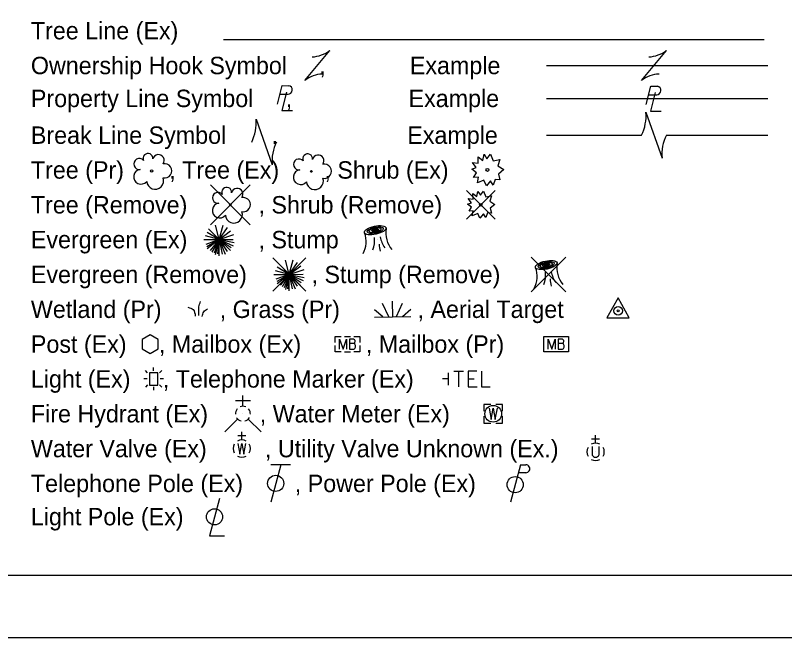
# Model space of a CAD drawing. Extents: x 0 to 34.3, y -4.1 to 22.
# Drawn here: x 8.07 to 14.26, y 0 to 5 of the extents above; entities that cross this region are included whole.
import ezdxf

# ---------------------------------------------------------------- set-up
doc = ezdxf.new("R2010")
doc.units = 0
for name, color, linetype in [('GM_X_Adjacent_County', 7, 'Continuous'), ('GM_X_County', 7, 'Continuous'), ('GM_X_Section', 7, 'Continuous')]:
    doc.layers.add(name, color=color, linetype=linetype)

msp = doc.modelspace()

# ---------------------------------------------------------------- linework, layer by layer
at = {"layer": 'GM_X_Adjacent_County'}
for p, q in [((9.7458, 4.8098), (14.0958, 4.8098)), ((10.4008, 4.4798), (10.6008, 4.7198)), ((13.109, 4.4798), (13.309, 4.7198)), ((10.5008, 4.5998), (10.5008, 4.5998)), ((12.3436, 4.5998), (14.1259, 4.5998)), ((13.209, 4.5998), (13.209, 4.5998)), ((10.2011, 4.3688), (10.2659, 4.3688)), ((10.2412, 4.3376), (10.2412, 4.3376)), ((12.3436, 4.3352), (14.1259, 4.3352)), ((13.1667, 4.3647), (13.2316, 4.3647)), ((13.2068, 4.3336), (13.2068, 4.3336)), ((13.144, 4.224), (13.274, 3.8558)), ((10.0084, 4.1684), (10.1384, 3.8001)), ((12.3436, 4.0398), (13.1091, 4.0398)), ((13.209, 4.0399), (13.209, 4.0399)), ((13.3089, 4.0398), (14.1259, 4.0398)), ((10.0734, 3.9842), (10.0734, 3.9842)), ((9.6412, 3.6401), (9.962, 3.3194)), ((9.962, 3.6401), (9.6412, 3.3194)), ((11.7003, 3.5957), (11.9321, 3.3639)), ((11.9321, 3.5957), (11.7003, 3.3639)), ((9.8016, 3.4798), (9.8016, 3.4798)), ((11.8162, 3.4798), (11.8162, 3.4798)), ((9.7121, 3.1996), (9.6248, 3.2868)), ((9.7121, 3.1996), (9.6812, 3.3149)), ((9.7121, 3.1996), (9.7435, 3.317)), ((9.7121, 3.1996), (9.7785, 3.2967)), ((9.7121, 3.1996), (9.6017, 3.2292)), ((9.7121, 3.1996), (9.6144, 3.257)), ((9.7121, 3.1996), (9.8035, 3.2697)), ((9.7121, 3.1996), (9.8305, 3.2398)), ((9.5887, 3.1996), (9.7121, 3.1996)), ((9.7121, 3.1996), (9.6048, 3.1605)), ((9.7121, 3.1996), (9.6125, 3.1425)), ((9.7121, 3.1996), (9.6144, 3.1247)), ((9.7121, 3.1996), (9.6385, 3.1129)), ((9.7121, 3.1996), (9.6541, 3.0992)), ((9.7121, 3.1996), (9.6705, 3.0911)), ((9.7121, 3.1996), (9.6805, 3.0782)), ((9.7121, 3.1996), (9.6985, 3.0848)), ((9.7121, 3.1996), (9.8248, 3.2019)), ((9.7121, 3.0686), (9.7121, 3.1996)), ((9.7121, 3.1996), (9.7351, 3.0837)), ((9.7121, 3.1996), (9.7604, 3.0829)), ((9.7121, 3.1996), (9.7755, 3.1048)), ((9.7121, 3.1996), (9.8018, 3.1115)), ((9.7121, 3.1996), (9.8076, 3.1357)), ((9.7121, 3.1996), (9.8237, 3.151)), ((9.7121, 3.1996), (9.8328, 3.1756)), ((10.9857, 3.1998), (10.9857, 3.1998)), ((10.1425, 3.0534), (10.4098, 2.7861)), ((10.4098, 3.0534), (10.1425, 2.7861)), ((10.2761, 2.9198), (10.2452, 3.0351)), ((10.2761, 2.9198), (10.3075, 3.0373)), ((12.2223, 3.0589), (12.5004, 2.7808)), ((12.5004, 3.0589), (12.2223, 2.7808)), ((10.2761, 2.9198), (10.1784, 2.9772)), ((10.2761, 2.9198), (10.1888, 3.007)), ((10.2761, 2.9198), (10.3425, 3.0169)), ((10.2761, 2.9198), (10.3675, 2.9899)), ((10.1527, 2.9198), (10.2761, 2.9198)), ((10.2761, 2.9198), (10.1658, 2.9494)), ((10.2761, 2.9198), (10.1688, 2.8808)), ((10.2761, 2.9198), (10.1765, 2.8628)), ((10.2761, 2.9198), (10.1784, 2.8449)), ((10.2761, 2.9198), (10.2025, 2.8331)), ((10.2761, 2.9198), (10.2181, 2.8194)), ((10.2761, 2.9198), (10.2345, 2.8113)), ((10.2761, 2.9198), (10.2445, 2.7984)), ((10.2761, 2.9198), (10.2626, 2.805)), ((10.2761, 2.9198), (10.3945, 2.96)), ((10.2761, 2.9198), (10.3888, 2.9221)), ((10.2761, 2.7888), (10.2761, 2.9198)), ((10.2761, 2.9198), (10.2991, 2.8039)), ((10.2761, 2.9198), (10.3244, 2.8031)), ((10.2761, 2.9198), (10.3395, 2.825)), ((10.2761, 2.9198), (10.3658, 2.8318)), ((10.2761, 2.9198), (10.3716, 2.8559)), ((10.2761, 2.9198), (10.3877, 2.8713)), ((10.2761, 2.9198), (10.3968, 2.8959)), ((10.2761, 2.9198), (10.2761, 2.9198)), ((12.3613, 2.9198), (12.3613, 2.9198)), ((12.3613, 2.9198), (12.3613, 2.9198)), ((11.0777, 2.5794), (11.0256, 2.6855)), ((11.1077, 2.5798), (11.1058, 2.7053)), ((11.1377, 2.5803), (11.1866, 2.6878)), ((11.029, 2.5787), (10.9607, 2.6358)), ((11.1864, 2.581), (11.253, 2.6401)), ((10.9616, 2.5776), (11.2538, 2.582)), ((10.7189, 2.4209), (10.7689, 2.4209)), ((10.7444, 2.3598), (10.7444, 2.3598)), ((12.4226, 2.3598), (12.4226, 2.3598)), ((10.7189, 2.2987), (10.7689, 2.2987)), ((9.1848, 2.1438), (9.1848, 2.1704)), ((9.1365, 2.1282), (9.118, 2.147)), ((9.2515, 2.147), (9.2329, 2.1282)), ((11.5574, 2.0298), (11.5574, 2.1298)), ((9.1326, 2.0801), (9.106, 2.0801)), ((9.1848, 2.0798), (9.1848, 2.0798)), ((9.2635, 2.0801), (9.2369, 2.0801)), ((11.5574, 2.0798), (11.5077, 2.0798)), ((9.1365, 2.0314), (9.118, 2.0126)), ((9.1848, 2.0158), (9.1848, 1.9892)), ((9.2515, 2.0126), (9.2329, 2.0314)), ((9.9028, 1.86), (9.9028, 1.946)), ((9.9628, 1.903), (9.8428, 1.903)), ((9.9029, 1.7998), (9.9029, 1.7998)), ((9.9029, 1.7998), (9.9029, 1.7998)), ((11.9165, 1.7998), (11.9165, 1.7998)), ((9.8606, 1.7574), (9.7566, 1.6535)), ((9.9452, 1.7574), (10.0492, 1.6535)), ((9.9255, 1.6216), (9.8619, 1.6216)), ((9.8938, 1.5898), (9.8938, 1.6534)), ((12.7399, 1.5634), (12.7399, 1.6269)), ((12.7717, 1.5952), (12.7081, 1.5952)), ((9.8938, 1.5198), (9.8938, 1.5198)), ((12.7127, 1.5365), (12.7127, 1.4676)), ((12.7399, 1.4934), (12.7399, 1.4934)), ((12.767, 1.5365), (12.767, 1.4676)), ((10.2068, 1.3898), (10.1265, 1.0898)), ((10.2868, 1.3898), (10.1268, 1.3898)), ((12.1358, 1.3898), (12.0554, 1.0898)), ((12.1358, 1.3898), (12.1783, 1.3898)), ((12.1187, 1.3261), (12.1783, 1.3261))]:
    msp.add_line(p, q, dxfattribs=at)
for points in [[(10.1801, 4.2892), (10.2192, 4.4375), (10.2708, 4.4374)], [(13.1457, 4.2851), (13.1848, 4.4334), (13.2365, 4.4333)], [(10.2545, 4.3856), (10.2149, 4.2378), (10.3023, 4.2378)], [(13.2201, 4.3816), (13.1806, 4.2337), (13.2679, 4.2337)], [(11.8649, 3.8503), (11.8952, 3.8871), (11.9159, 3.8344), (11.9705, 3.8434), (11.9536, 3.7928), (12.0009, 3.7631), (11.958, 3.7263), (11.9705, 3.6806), (11.9329, 3.6841), (11.9166, 3.6384), (11.8952, 3.673), (11.8613, 3.6321), (11.8399, 3.6765), (11.7889, 3.655), (11.7984, 3.7021), (11.7579, 3.6979), (11.7815, 3.7374), (11.7431, 3.7658), (11.78, 3.779), (11.7497, 3.8191), (11.7963, 3.8136), (11.7948, 3.8656), (11.8324, 3.8371), (11.8428, 3.8864), (11.8649, 3.8503)], [(11.8126, 3.5567), (11.8383, 3.588), (11.8559, 3.5432), (11.9023, 3.5509), (11.888, 3.5079), (11.9281, 3.4826), (11.8917, 3.4513), (11.9023, 3.4125), (11.8703, 3.4154), (11.8565, 3.3766), (11.8383, 3.406), (11.8095, 3.3713), (11.7913, 3.409), (11.7479, 3.3907), (11.7561, 3.4307), (11.7216, 3.4272), (11.7417, 3.4608), (11.709, 3.4849), (11.7404, 3.4961), (11.7146, 3.5302), (11.7542, 3.5256), (11.753, 3.5697), (11.785, 3.5455), (11.7938, 3.5874), (11.8126, 3.5567)], [(9.0916, 2.3223), (9.1565, 2.2848), (9.2214, 2.3223), (9.2214, 2.3973), (9.1565, 2.4348), (9.0916, 2.3973), (9.0916, 2.3223)], [(10.6444, 2.3724), (10.6444, 2.4209), (10.6929, 2.4209)], [(10.7948, 2.4209), (10.8444, 2.4209), (10.8444, 2.3724)], [(10.6796, 2.3198), (10.6796, 2.3998), (10.7086, 2.3198), (10.7363, 2.3998), (10.7363, 2.3198)], [(10.7955, 2.3633), (10.7987, 2.3664), (10.8006, 2.3683), (10.8018, 2.3702), (10.8025, 2.3715), (10.8037, 2.374), (10.8044, 2.3759), (10.8056, 2.3803), (10.8056, 2.3822), (10.8056, 2.3847), (10.805, 2.3885), (10.8037, 2.3916), (10.8018, 2.3941), (10.7987, 2.3967), (10.7962, 2.3979), (10.7949, 2.3986), (10.7918, 2.3998), (10.7609, 2.3998), (10.7609, 2.3198), (10.7955, 2.3198), (10.7999, 2.3223), (10.8037, 2.3255), (10.8069, 2.3305), (10.8088, 2.3362), (10.8094, 2.3419), (10.8094, 2.3456), (10.8081, 2.3494), (10.8056, 2.3551), (10.8025, 2.3589), (10.7955, 2.3633), (10.7609, 2.3633)], [(12.3578, 2.3198), (12.3578, 2.3998), (12.3867, 2.3198), (12.4144, 2.3998), (12.4144, 2.3198)], [(12.4737, 2.3633), (12.4768, 2.3664), (12.4787, 2.3683), (12.48, 2.3702), (12.4806, 2.3715), (12.4818, 2.374), (12.4825, 2.3759), (12.4837, 2.3803), (12.4837, 2.3822), (12.4837, 2.3847), (12.4831, 2.3885), (12.4818, 2.3916), (12.48, 2.3941), (12.4768, 2.3967), (12.4743, 2.3979), (12.473, 2.3986), (12.4699, 2.3998), (12.439, 2.3998), (12.439, 2.3198), (12.4737, 2.3198), (12.4781, 2.3223), (12.4818, 2.3255), (12.485, 2.3305), (12.4869, 2.3362), (12.4875, 2.3419), (12.4875, 2.3456), (12.4863, 2.3494), (12.4837, 2.3551), (12.4806, 2.3589), (12.4737, 2.3633), (12.439, 2.3633)], [(10.6929, 2.2987), (10.6444, 2.2987), (10.6444, 2.3472)], [(10.8444, 2.3472), (10.8444, 2.2987), (10.7948, 2.2987)], [(11.5983, 2.1419), (11.676, 2.1419)], [(11.6376, 2.1419), (11.6376, 2.0169)], [(11.7833, 2.1419), (11.7154, 2.1419), (11.7154, 2.0169), (11.7882, 2.0169)], [(11.8226, 2.1419), (11.8226, 2.0169), (11.8906, 2.0169)], [(11.7154, 2.0799), (11.7636, 2.0799)], [(11.8965, 1.8748), (11.8415, 1.8748), (11.8415, 1.8198)], [(11.9915, 1.8198), (11.9915, 1.8748), (11.9365, 1.8748)], [(11.8831, 1.8448), (11.8998, 1.7548), (11.9165, 1.8448), (11.9331, 1.7548), (11.9498, 1.8448)], [(11.8415, 1.7798), (11.8415, 1.7248), (11.8965, 1.7248)], [(11.9365, 1.7248), (11.9915, 1.7248), (11.9915, 1.7798)], [(9.8619, 1.5608), (9.8778, 1.4746), (9.8938, 1.5608), (9.9098, 1.4746), (9.9256, 1.5608)], [(9.714, 1.1186), (9.6353, 0.8193), (9.7535, 0.8193)]]:
    msp.add_lwpolyline(points, dxfattribs=at)
for points in [[(12.8307, 2.5698), (13.0107, 2.5698), (12.9207, 2.7308)], [(12.3226, 2.4209), (12.5226, 2.4209), (12.5226, 2.2987), (12.3226, 2.2987)], [(9.1515, 2.0298), (9.218, 2.0298), (9.218, 2.1298), (9.1515, 2.1298)]]:
    msp.add_lwpolyline(points, close=True, dxfattribs=at)
for centre, radius in [((9.1686, 3.7517), 0.0084), ((10.4532, 3.7483), 0.0072), ((11.8692, 3.7598), 0.0115), ((9.8016, 3.4798), 0.0072), ((11.8162, 3.4798), 0.00979), ((12.9207, 2.6276), 0.035), ((12.9207, 2.6276), 0.008), ((11.9165, 1.7998), 0.0675), ((10.1666, 1.2398), 0.065), ((12.0929, 1.2298), 0.065), ((9.6747, 0.9709), 0.065)]:
    msp.add_circle(centre, radius, dxfattribs=at)
for centre, radius, start, end in [((10.4427, 4.9348), 0.2668, 273.69448, 306.33701), ((13.1509, 4.9348), 0.2668, 273.69448, 306.33701), ((10.5589, 4.2649), 0.2668, 93.69448, 126.33701), ((13.2671, 4.2649), 0.2668, 93.69448, 126.33701), ((10.2656, 4.4033), 0.0345, 270.47098, 81.3281), ((13.2313, 4.3992), 0.0345, 270.47098, 81.3281), ((12.8121, 4.1915), 0.3335, 332.94224, 5.58476), ((9.6764, 4.1359), 0.3335, 332.94224, 5.58476), ((13.606, 3.8882), 0.3335, 152.94224, 185.58476), ((10.4703, 3.8326), 0.3335, 152.94224, 185.58476), ((9.0693, 3.8076), 0.0441, 39.06254, 279.54124), ((9.1391, 3.8527), 0.0395, 354.0047, 205.97412), ((9.2234, 3.8366), 0.0466, 323.82996, 165.0376), ((10.3539, 3.8042), 0.0441, 39.06254, 279.54124), ((10.4237, 3.8493), 0.0395, 354.0047, 205.97412), ((10.508, 3.8331), 0.0466, 323.82996, 165.0376), ((9.2724, 3.7528), 0.0574, 259.14531, 101.45961), ((10.557, 3.7493), 0.0574, 259.14531, 101.45961), ((9.083, 3.7052), 0.0592, 96.17219, 320.57371), ((10.3676, 3.7018), 0.0592, 96.17219, 320.57371), ((9.197, 3.6735), 0.0685, 184.94757, 19.45715), ((10.4816, 3.6701), 0.0685, 184.94757, 19.45715), ((9.7721, 3.5808), 0.0395, 354.0047, 205.97412), ((9.8564, 3.5647), 0.0466, 323.82996, 165.0376), ((9.7023, 3.5357), 0.0441, 39.06254, 279.54124), ((9.9054, 3.4809), 0.0574, 259.14531, 101.45961), ((9.716, 3.4333), 0.0592, 96.17219, 320.57371), ((9.83, 3.4016), 0.0685, 184.94757, 19.45715), ((11.266, 3.2569), 0.2146, 171.41061, 219.91939), ((10.6941, 3.1825), 0.2001, 331.53375, 20.92689), ((11.3111, 3.3026), 0.316, 194.9653, 212.12159), ((10.7099, 3.2011), 0.2527, 340.79377, 3.54808), ((11.181, 3.1598), 0.1819, 178.79264, 197.12241), ((12.0697, 2.9025), 0.2001, 331.53375, 20.92689), ((12.6416, 2.9769), 0.2146, 171.41061, 219.91939), ((12.0855, 2.9211), 0.2527, 340.79377, 3.54808), ((12.6867, 3.0226), 0.316, 194.9653, 212.12159), ((12.5566, 2.8798), 0.1819, 178.79264, 197.12241), ((9.9029, 1.7998), 0.06, 68.13946, 112.03798), ((9.9029, 1.7998), 0.06, 140.02099, 184.06293), ((9.9029, 1.7998), 0.06, 356.01648, 39.98885), ((9.9029, 1.7998), 0.06, 211.87877, 255.84793), ((9.9029, 1.7998), 0.06, 283.82389, 329.90967), ((9.8937, 1.5199), 0.07, 150.01836, 209.98164), ((9.8937, 1.5199), 0.07, 60.01836, 120.01574), ((9.8937, 1.5199), 0.07, 330.01836, 29.98164), ((12.7399, 1.4935), 0.07, 60.01836, 120.01574), ((12.7399, 1.4935), 0.07, 150.01836, 209.98164), ((12.7399, 1.4935), 0.07, 330.01836, 29.98164), ((9.8937, 1.5199), 0.07, 239.98426, 299.98164), ((12.7399, 1.4935), 0.07, 239.98426, 299.98164), ((12.7399, 1.4804), 0.03, 205.19243, 334.80757), ((12.1789, 1.3579), 0.0319, 268.8767, 91.1233)]:
    msp.add_arc(centre, radius, start, end, dxfattribs=at)
for centre, major_axis in [((10.967, 3.2754), (0.0868, 0.0187)), ((10.967, 3.2754), (0.0651, 0.0141)), ((10.967, 3.2754), (0.0488, 0.0105)), ((10.967, 3.2754), (0.0275, 0.0059)), ((10.967, 3.2754), (0.0154, 0.0033)), ((12.3426, 2.9954), (0.0868, 0.0187)), ((12.3426, 2.9954), (0.0651, 0.0141)), ((12.3426, 2.9954), (0.0488, 0.0105)), ((12.3426, 2.9954), (0.0275, 0.0059)), ((12.3426, 2.9954), (0.0154, 0.0033))]:
    msp.add_ellipse(centre, major_axis=major_axis, ratio=0.36865, dxfattribs=at)
for points in [[(9.5482, 2.5884), (9.5482, 2.6357), (9.5541, 2.6801), (9.5629, 2.7009)], [(9.4608, 2.6554), (9.5022, 2.6377), (9.52, 2.5844)], [(9.5759, 2.5812), (9.5877, 2.6196), (9.6172, 2.6434)]]:
    msp.add_spline(points, degree=3, dxfattribs=at)
at = {"layer": 'GM_X_County'}
msp.add_lwpolyline([(1.5, 21.5), (33.5, 21.5), (33.5, 0.5), (1.5, 0.5)], close=True, dxfattribs=at)
at = {"layer": 'GM_X_Section'}
msp.add_lwpolyline([(0, 0), (34, 0), (34, 22), (0, 22)], close=True, dxfattribs=at)

# ---------------------------------------------------------------- texts
at = {"layer": 'GM_X_Adjacent_County'}
for s, p in [('Tree Line (Ex)', (8.1973, 4.8098)), ('Ownership Hook Symbol     ,             Example', (8.1973, 4.5298)), ('Property Line Symbol     ,                  Example', (8.1973, 4.2652)), ('Break Line Symbol       ,                    Example', (8.1973, 3.9698)), ('Tree (Pr)       , Tree (Ex)       , Shrub (Ex)', (8.1973, 3.6898)), ('Tree (Remove)           , Shrub (Remove)', (8.1973, 3.4098)), ('Evergreen (Ex)           , Stump ', (8.1973, 3.1298)), ('Evergreen (Remove)          , Stump (Remove)', (8.1973, 2.8498)), ('Wetland (Pr)         , Grass (Pr)            , Aerial Target    ', (8.1973, 2.5698)), ('Post (Ex)     , Mailbox (Ex)          , Mailbox (Pr)', (8.1973, 2.2898)), ('Light (Ex)     , Telephone Marker (Ex)     ', (8.1973, 2.0098)), ('Fire Hydrant (Ex)        , Water Meter (Ex)', (8.1973, 1.7298)), ('Water Valve (Ex)         , Utility Valve Unknown (Ex.)', (8.1973, 1.4498)), ('Telephone Pole (Ex)        , Power Pole (Ex)', (8.1973, 1.1698)), ('Light Pole (Ex)     ', (8.1973, 0.9027))]:
    msp.add_text(s, height=0.14, dxfattribs=at).set_placement(p)

doc.saveas('drawing.dxf')
